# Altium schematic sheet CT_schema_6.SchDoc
size 293 x 258 mm
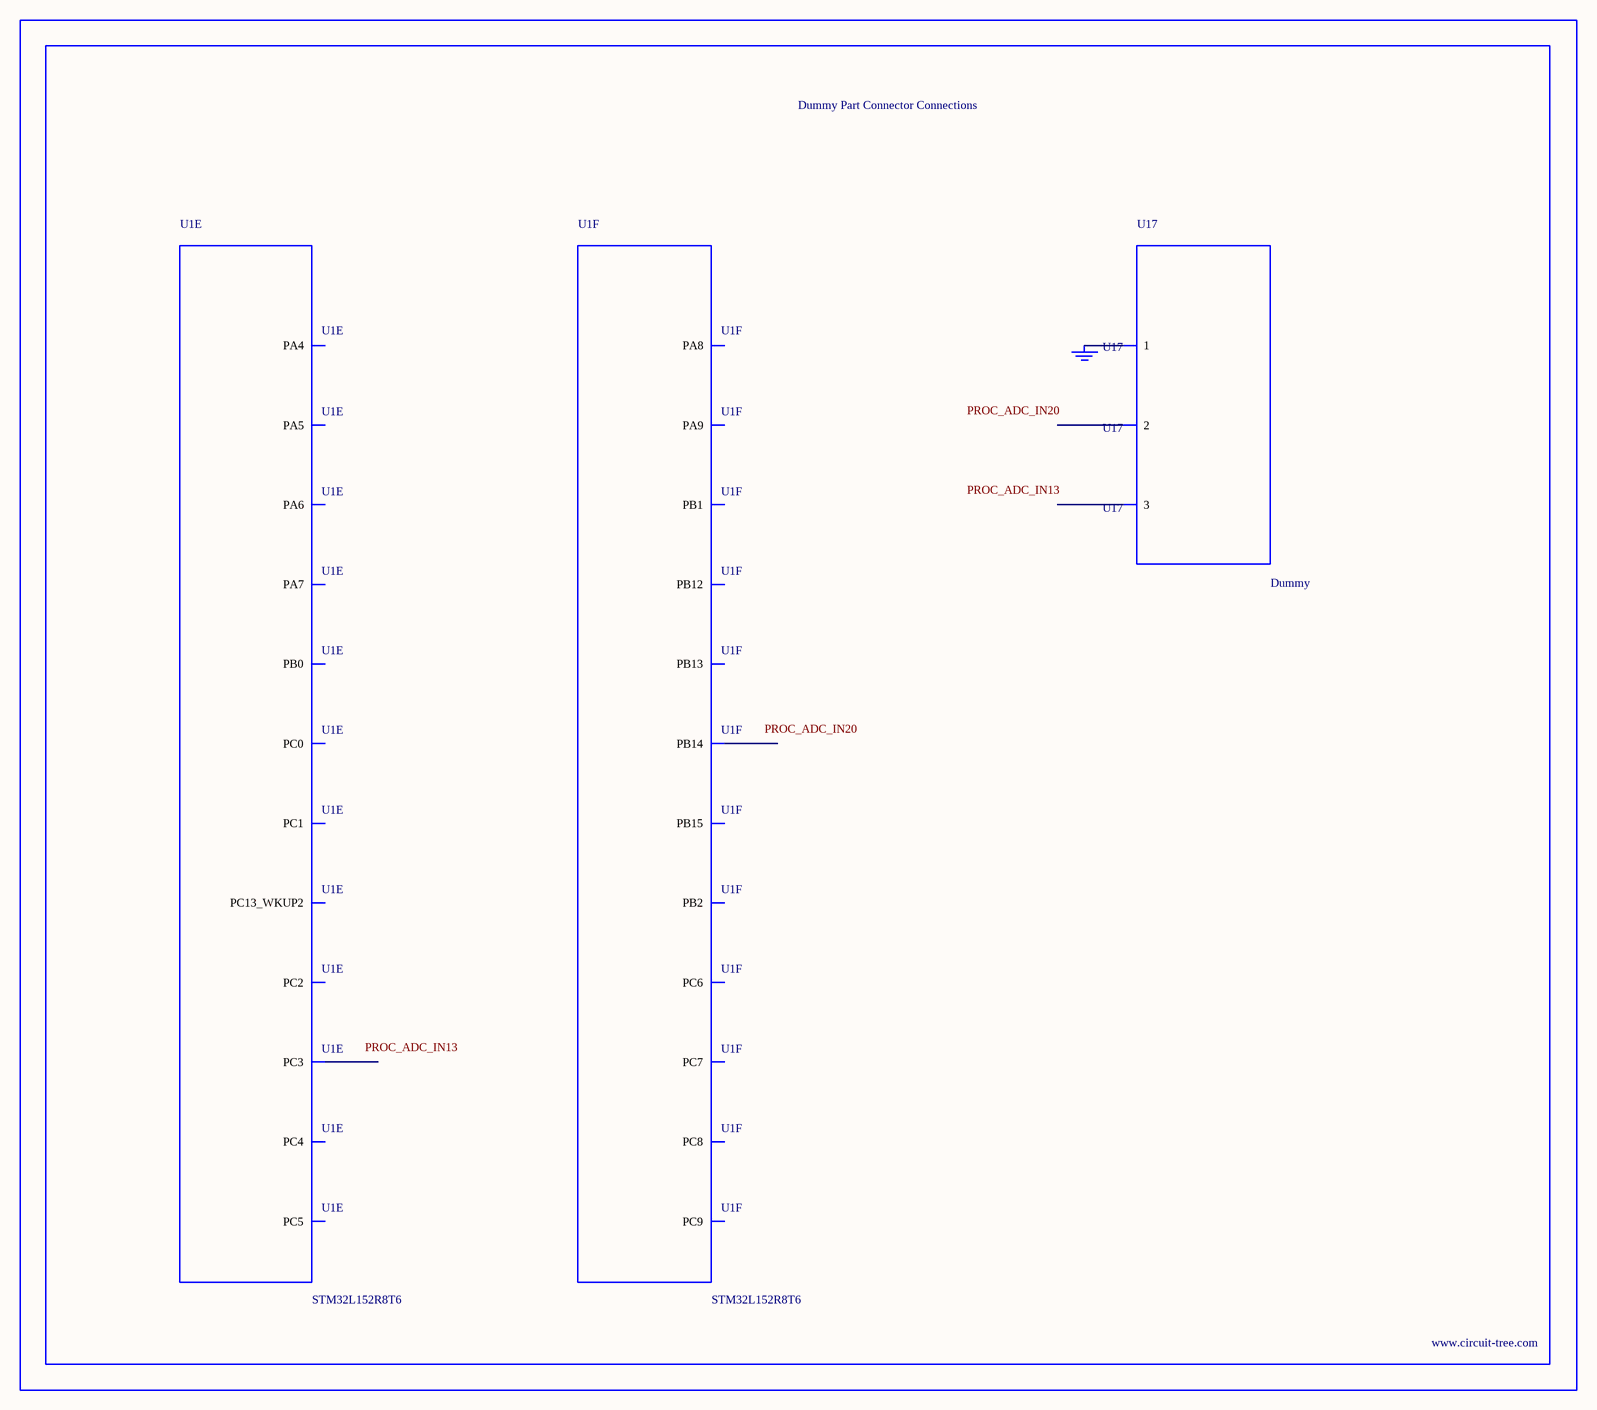
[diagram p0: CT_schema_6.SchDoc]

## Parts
BORDER5  (no value)
GND_INSTANCE_5_0  (no value)
U1  STM32L152R8T6  [LQFP64]  (parts E,F of 6)
U17  Dummy  [DUMMY_PACKAGE_144]

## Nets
NetGND_INSTANCE_5_0_0: GND_INSTANCE_5_0.0(GND) U17.1

Not connected (* = marked no-connect by the designer): U1 2(PC13_WKUP2) 8(PC0) 9(PC1) 10(PC2) 11(PC3) 20(PA4) 21(PA5) 22(PA6) 23(PA7) 24(PC4) 25(PC5) 26(PB0) 27(PB1) 28(PB2) 33(PB12) 34(PB13) 35(PB14) 36(PB15) 37(PC6) 38(PC7) 39(PC8) 40(PC9) 41(PA8) 42(PA9); U17 2 3

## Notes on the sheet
- Labels drawn without touching a wire or pin: PROC_ADC_IN13, PROC_ADC_IN20

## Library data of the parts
BORDER5 = BORDER_PAGE5
GND_INSTANCE_5_0 = GND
